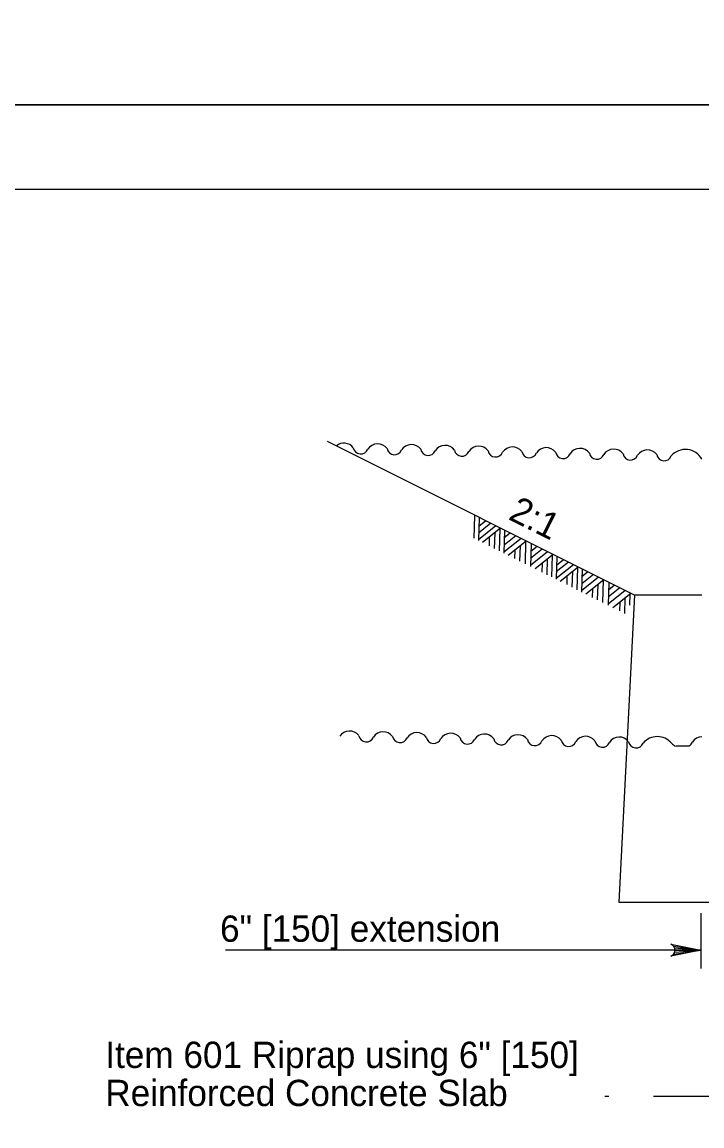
# Model space of a CAD drawing. Extents: x 1083.1 to 1117.1, y 675.4 to 741.4.
# Drawn here: x 1103.17 to 1107.2, y 691.3 to 697.84 of the extents above; entities that cross this region are included whole.
import ezdxf

# ---------------------------------------------------------------- set-up
doc = ezdxf.new("R2010")
doc.units = 0
doc.layers.add('Level 1', color=7, linetype='Continuous')

msp = doc.modelspace()

# ---------------------------------------------------------------- linework, layer by layer
at = {"layer": 'Level 1'}
for p, q in [((1117.1264, 697.3541), (1083.1264, 697.3541)), ((1106.7999, 694.4455), (1104.9778, 695.3563)), ((1105.8502, 694.9203), (1105.8484, 694.8473)), ((1105.878, 694.9064), (1105.874, 694.7701)), ((1105.8484, 694.8473), (1105.8463, 694.7838)), ((1105.9777, 694.8566), (1105.8745, 694.7741)), ((1105.9475, 694.8717), (1105.8753, 694.8136)), ((1105.9182, 694.8863), (1105.8764, 694.8526)), ((1106.0051, 694.8428), (1105.8985, 694.7574)), ((1106.0017, 694.8402), (1105.9979, 694.708)), ((1106.0286, 694.8311), (1106.0251, 694.6945)), ((1105.9388, 694.7901), (1105.9372, 694.7385)), ((1105.971, 694.8157), (1105.9681, 694.723)), ((1106.1269, 694.782), (1106.0253, 694.7012)), ((1106.0952, 694.7977), (1106.0264, 694.7424)), ((1106.0629, 694.8139), (1106.0275, 694.7853)), ((1106.1576, 694.7667), (1106.0509, 694.6816)), ((1106.0909, 694.7127), (1106.0891, 694.6625)), ((1106.1216, 694.7378), (1106.1187, 694.6477)), ((1106.1544, 694.7642), (1106.1507, 694.6318)), ((1106.1863, 694.7523), (1106.1827, 694.6157)), ((1106.2848, 694.7031), (1106.1827, 694.6222)), ((1106.253, 694.7189), (1106.1837, 694.6637)), ((1106.2218, 694.7346), (1106.185, 694.7051)), ((1106.3175, 694.6866), (1106.2112, 694.6015)), ((1106.2519, 694.634), (1106.2498, 694.5821)), ((1106.2826, 694.6585), (1106.2802, 694.567)), ((1106.3111, 694.6812), (1106.3095, 694.6168)), ((1106.3388, 694.6759), (1106.3348, 694.5396)), ((1106.4084, 694.6413), (1106.3364, 694.5831)), ((1106.3791, 694.6558), (1106.3375, 694.6222)), ((1106.3095, 694.6168), (1106.3073, 694.5534)), ((1106.4385, 694.6261), (1106.3356, 694.5436)), ((1106.4662, 694.6123), (1106.3593, 694.5269)), ((1106.4318, 694.5852), (1106.4289, 694.4926)), ((1106.4627, 694.6097), (1106.4588, 694.4776)), ((1106.4894, 694.6007), (1106.4859, 694.464)), ((1106.5238, 694.5834), (1106.4886, 694.5548)), ((1106.3998, 694.5596), (1106.398, 694.508)), ((1106.5877, 694.5515), (1106.4865, 694.4707)), ((1106.5563, 694.5673), (1106.4872, 694.5119)), ((1106.6184, 694.5362), (1106.5118, 694.4511)), ((1106.5824, 694.5073), (1106.5795, 694.4172)), ((1106.6155, 694.5338), (1106.6115, 694.4013)), ((1106.6472, 694.5217), (1106.6435, 694.3852)), ((1106.6827, 694.5041), (1106.6462, 694.4747)), ((1106.5521, 694.4823), (1106.5499, 694.4321)), ((1106.7456, 694.4727), (1106.6437, 694.3917)), ((1106.7141, 694.4884), (1106.6448, 694.4332)), ((1106.7786, 694.4561), (1106.672, 694.371)), ((1106.7999, 694.4455), (1106.7067, 692.6236)), ((1106.7722, 694.4507), (1106.7703, 694.3863)), ((1107.2008, 694.4455), (1106.7999, 694.4455)), ((1106.7127, 694.4036), (1106.7109, 694.3517)), ((1106.7434, 694.4281), (1106.7413, 694.3365)), ((1107.048, 693.5513), (1107.1258, 693.5513)), ((1106.7067, 692.6236), (1107.468, 692.6236)), ((1107.1477, 692.6236), (1107.2008, 692.6236)), ((1107.194, 692.5591), (1107.194, 692.2302)), ((1107.0317, 692.3642), (1107.1938, 692.3393)), ((1107.0378, 692.3537), (1107.1938, 692.3393)), ((1107.1938, 692.3393), (1104.3727, 692.3393)), ((1107.0336, 692.3169), (1107.1938, 692.3393)), ((1107.0391, 692.328), (1107.1938, 692.3393)), ((1107.0407, 692.3393), (1107.1938, 692.3393)), ((1106.6245, 691.4732), (1106.6479, 691.4732)), ((1106.9131, 691.4732), (1108.1757, 691.4732))]:
    msp.add_line(p, q, dxfattribs=at)
for points in [[(1083.1264, 697.3541), (1117.1264, 697.3541), (1117.1264, 719.3541), (1083.1264, 719.3541)], [(1083.1264, 697.3541), (1117.1264, 697.3541), (1117.1264, 719.3541), (1083.1264, 719.3541)], [(1085.1264, 696.8541), (1116.6264, 696.8541), (1116.6264, 675.8541), (1085.1264, 675.8541)]]:
    msp.add_lwpolyline(points, close=True, dxfattribs=at)
msp.add_lwpolyline([(1107.0168, 692.3747), (1107.1938, 692.3393), (1107.0168, 692.3039)], dxfattribs=at)
msp.add_arc((1107.0026, 692.3393), 0.0382, 292.08782, 67.91395, dxfattribs=at)
for centre, major_axis, start_param, end_param in [((1105.0757, 695.2773), (0.0701, 0), 0.651838, 2.265162), ((1105.1756, 695.3276), (0.0448, 0), 3.31542, 5.913716), ((1105.2759, 695.2728), (0.0701, 0), 0.651838, 2.558608), ((1105.3758, 695.3231), (0.0448, 0), 3.31542, 5.913716), ((1105.476, 695.2683), (0.0701, 0), 0.651838, 2.558608), ((1105.576, 695.3187), (0.0448, 0), 3.31542, 5.913716), ((1105.6762, 695.2639), (0.0701, 0), 0.651838, 2.558608), ((1105.7759, 695.3142), (0.0448, 0), 3.31542, 5.913716), ((1105.8764, 695.2594), (0.0701, 0), 0.651838, 2.558608), ((1105.9761, 695.3097), (0.0448, 0), 3.31542, 5.913716), ((1106.0765, 695.2549), (0.0701, 0), 0.651838, 2.558608), ((1106.1762, 695.3052), (0.0448, 0), 3.31542, 5.913716), ((1106.2767, 695.2504), (0.0701, 0), 0.651838, 2.558608), ((1106.3764, 695.3007), (0.0448, 0), 3.31542, 5.913716), ((1106.4769, 695.2459), (0.0701, 0), 0.651838, 2.558608), ((1106.6768, 695.2414), (0.0701, 0), 0.651838, 2.558608), ((1106.877, 695.2369), (0.0701, 0), 0.651838, 2.558608), ((1107.103, 695.1989), (-0.111, 0), 3.633123, 5.574882), ((1106.5766, 695.2962), (0.0448, 0), 3.31542, 5.913716), ((1106.7767, 695.2917), (0.0448, 0), 3.31542, 5.913716), ((1106.9769, 695.2872), (0.0448, 0), 3.31542, 5.913716), ((1105.109, 693.5696), (0.0701, 0), 0.651838, 2.558608), ((1105.2087, 693.6198), (0.0448, 0), 3.31542, 5.913716), ((1105.3089, 693.5651), (0.0701, 0), 0.651838, 2.558608), ((1105.4089, 693.6154), (0.0448, 0), 3.31542, 5.913716), ((1105.5091, 693.5606), (0.0701, 0), 0.651838, 2.558608), ((1105.609, 693.6109), (0.0448, 0), 3.31542, 5.913716), ((1105.7092, 693.5561), (0.0701, 0), 0.651838, 2.558608), ((1105.8092, 693.6064), (0.0448, 0), 3.31542, 5.913716), ((1105.9094, 693.5516), (0.0701, 0), 0.651838, 2.558608), ((1106.0094, 693.6019), (0.0448, 0), 3.31542, 5.913716), ((1106.1096, 693.5471), (0.0701, 0), 0.651838, 2.558608), ((1106.2095, 693.5974), (0.0448, 0), 3.31542, 5.913716), ((1106.3098, 693.5426), (0.0701, 0), 0.651838, 2.558608), ((1106.5099, 693.5381), (0.0701, 0), 0.651838, 2.558608), ((1106.7101, 693.5336), (0.0701, 0), 0.651838, 2.558608), ((1106.9359, 693.4956), (-0.111, 0), 3.847218, 5.574882), ((1107.2032, 693.5359), (0.0701, 0), 1.605642, 2.558608), ((1106.4097, 693.5929), (0.0448, 0), 3.31542, 5.913716), ((1106.6099, 693.5884), (0.0448, 0), 3.31542, 5.913716), ((1106.8098, 693.584), (0.0448, 0), 3.31542, 5.913716), ((1107.0699, 693.6079), (0.064, 0), 3.825122, 4.301892), ((1107.103, 693.5907), (0.0448, 0), 5.211382, 5.913717)]:
    msp.add_ellipse(centre, major_axis=major_axis, ratio=0.999895, start_param=start_param, end_param=end_param, dxfattribs=at)

# ---------------------------------------------------------------- texts
msp.add_text('2:1', height=0.156, rotation=333.43737, dxfattribs=at).set_placement((1106.0456, 694.8985))
for s, p in [('6" [150] extension', (1104.3404, 692.3895)), ('Item 601 Riprap using 6" [150]', (1103.6593, 691.6409)), ('Reinforced Concrete Slab', (1103.6593, 691.4149))]:
    msp.add_text(s, height=0.156, dxfattribs=at).set_placement(p)

doc.saveas('drawing.dxf')
